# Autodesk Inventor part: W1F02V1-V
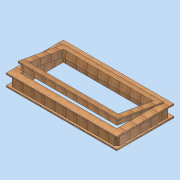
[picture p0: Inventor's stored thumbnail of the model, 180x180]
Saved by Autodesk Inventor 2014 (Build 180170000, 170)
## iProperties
Created: 2011-04
Part Number: W1F02V1-V
Document SubType Name: Modeling
Designer: david.appleford
Density: 0.60521 g/cm^3
Description: Window 900 x 450 Type A 1 Panel
Mass: 10000 g
Surface Area: 13455.6 cm^2
Volume: 16523.2 cm^3
Cost Center: £135.00
Material: 000 Redwood
Appearance: Wood (Oak)
Justset: False
Author: david.appleford
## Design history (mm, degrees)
sketch "Sketch1"
  geometry: L1 (466, 857)-(466, 407); L2 (466, 407)-(-434, 407); L3 (-434, 407)-(-434, 857); L4 (-434, 857)-(466, 857); L5 (592, 1202)-(592, -1170); L6 (-560, 1202)-(592, 1202); L7 (-560, -1170)-(-560, 1202); L8 (592, -1170)-(-560, -1170); L9 (481, 872)-(481, 392); L10 (481, 392)-(-449, 392); L11 (-449, 392)-(-449, 872); L12 (-449, 872)-(481, 872); L13 (422, 813)-(422, 451); L14 (422, 451)-(-390, 451); L15 (-390, 451)-(-390, 813); L16 (-390, 813)-(422, 813); 1 further point
  constraints: 32 end point, 6 other
  dimensions: "d0" = 15 distance between parallel lines of L4 L12; "d1" = 44 distance between parallel lines of L15 L3; "d31" = 345 distance between parallel lines of L6 L4; "d32" = 2372 distance between parallel lines of L6 L8; "d33" = 1152 distance between parallel lines of L5 L7; "d34" = 900 distance between parallel lines of L1 L3; "d35" = 126 distance between parallel lines of L3 L7 (= -0.5 x d34 + 0.5 x d33); "d36" = 450 distance between parallel lines of L4 L2
extrude "Extrusion1" new body sketch "Sketch1" distance "d2" = 12; taper "d3" = 0 deg
workplane "Work Plane1"
sketch "Sketch2"
  geometry: L1 (-481, 872)-(-481, 392) reference; L2 (449, 872)-(-481, 872) reference; L3 (449, 392)-(449, 872) reference; L4 (-481, 392)-(449, 392) reference; L5 (-422, 451)-(-422, 813) reference; L6 (-422, 813)-(390, 813) reference; L7 (390, 813)-(390, 451) reference; L8 (390, 451)-(-422, 451) reference; 1 further point
extrude "Extrusion2" join sketch "Sketch2" distance "d4" = 12; taper "d5" = 0 deg
sketch "Sketch3"
  geometry: L1 (-422, 813)-(390, 813) reference; L2 (-422, 451)-(-422, 813) reference; L3 (390, 451)-(-422, 451) reference; L4 (390, 813)-(390, 451) reference; L5 (434, 857)-(434, 407); L6 (-466, 857)-(434, 857); L7 (-466, 407)-(-466, 857); L8 (434, 407)-(-466, 407); L9 (-481, 872)-(-481, 392) reference; L10 (-481, 392)-(449, 392) reference; L11 (449, 872)-(-481, 872) reference; 1 further point
  constraints: 8 end point
  dimensions: "d37" = 900 distance between parallel lines of L7 L5; "d38" = 15 distance between parallel lines of L9 L7; "d39" = 15 distance between parallel lines of L8 L10 (= d38); "d40" = 15 distance between parallel lines of L11 L6 (= d38)
workplane "Work Plane2"
extrude "Extrusion3" join sketch "Sketch3" stored distance "d6" = 12; taper "d7" = 0 deg
sketch "Sketch5"
  geometry: L1 (0, -59)-(0, 421) reference; L2 (-12, 421)-(0, 421) reference; L3 (-12, -59)-(-12, 421) reference; L4 (-12, -59)-(0, -59) reference; L5 (0, 362)-(-104, 362) reference; L6 (0, 377.231)-(67.375, -4.874); L7 (2.605, 362.459)-(-40.727, 354.819); L8 (-40.727, 354.819)-(21.439, 2.258); L9 (21.439, 2.258)-(64.771, 9.898); L10 (0, 377.231)-(11.818, 379.315); L11 (11.818, 379.315)-(79.193, -2.79); L12 (79.193, -2.79)-(67.375, -4.874); L13 (0, 421)-(0, -59) reference
  constraints: 14 end point, 4 perpendicular, 4 point on line, 2 parallel
  dimensions: "d13" = 15 distance from line of L7 L6.start; "d15" = 358 distance between parallel lines of L9 L7; "d16" = 15 distance from line of L6.end L9; "d17" = 12 distance between parallel lines of L6 L11; "d18" = 44 distance between parallel lines of L8 L6; "d41" = 10 deg angle of L1 L6
extrude "Extrusion5" join sketch "Sketch5" stored distance "d19" = 10; taper "d20" = 0 deg
sketch "Sketch6"
  geometry: L1 (812, 0)-(812, 12) reference; L2 (812, 12)-(827, 12); L3 (827, 12)-(827, 0); L4 (827, 0)-(812, 0); L5 (812, 0)-(812, 12); L6 (0, 12)-(0, 0) reference; L7 (0, 12)-(-15, 12); L8 (-15, 12)-(-15, 0); L9 (-15, 0)-(0, 0); L10 (0, 0)-(0, 12); L11 (812, 0)-(0, 0) reference; 1 further point
  constraints: 16 end point, 4 parallel, 2 collinear, 2 horizontal, 2 perpendicular
  dimensions: "d21" = 15 distance between parallel lines of L8 L10; "d22" = 15 distance between parallel lines of L3 L1
extrude "Extrusion6" join sketch "Sketch6" stored distance "d23" = 10; taper "d24" = 0 deg
sketch "Sketch7"
  geometry: L1 (812, -358)-(812, -234.536) reference; L2 (812, 0)-(812, -234.536) reference; L3 (0, 0)-(812, 0) reference; L4 (0, -234.536)-(0, 0) reference; L5 (0, -234.536)-(0, -358) reference; L6 (0, -358)-(812, -358) reference; L7 (783, -29)-(783, -329); L8 (783, -329)-(29, -329); L9 (29, -329)-(29, -217.639); L10 (29, -217.639)-(29, -29); L11 (29, -29)-(783, -29); L12 (-15, -373)-(-15, 15) reference; L13 (827, -373)-(827, 15) reference; 1 further point
  constraints: 10 end point, 3 other
  dimensions: "d25" = 44 distance between parallel lines of L10 L12; "d42" = 44 distance between parallel lines of L13 L7 (= d25)
extrude "Extrusion7" cut sketch "Sketch7" stored distance "d26" = 10; taper "d27" = 0 deg
chamfer "Chamfer1" distance "d28" = 20; stored, may be unused: second distance "d29" = 2, angle "d30" = 45 deg
body "Solid1"
node "Projected Loop1"
node "Projected Loop2"
other parameters: "d49" = 44, "d50" = 12, "d53" = 10 deg
